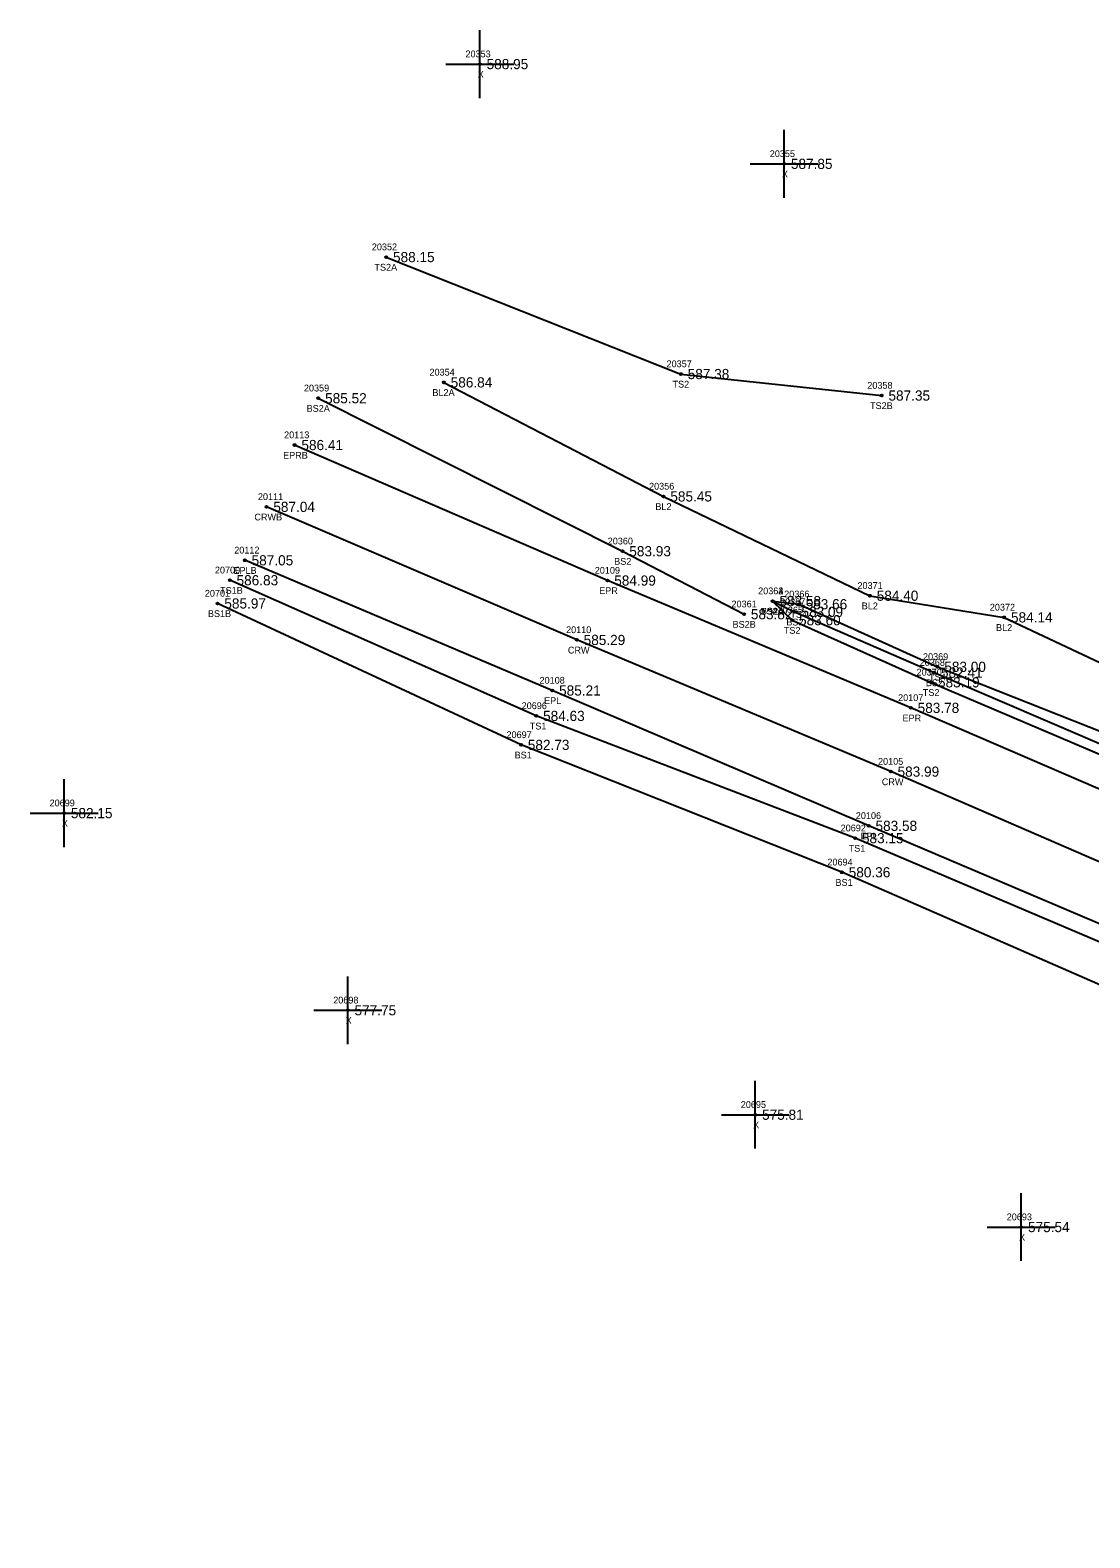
# Model space of a CAD drawing. Extents: x 1664837 to 1666270, y 987403 to 988245.
# Drawn here: x 1664836.6 to 1664992.8, y 987882.7 to 988105 of the extents above; entities that cross this region are included whole.
import ezdxf

# ---------------------------------------------------------------- set-up
doc = ezdxf.new("R2010")
doc.units = 0
for name, color, linetype in [('RD_DTM_BkLn1', 7, 'Continuous'), ('RD_DTM_BkLn2', 7, 'Continuous'), ('RD_DTM_BkLn_txCode', 7, 'Continuous'), ('RD_EX_Misc', 7, 'Continuous'), ('RD_EX_Misc_txCode', 7, 'Continuous'), ('RD_EX_Road', 7, 'Continuous'), ('RD_EX_Road_txCode', 7, 'Continuous'), ('RD_EX_TX_Misc_ELEV', 7, 'Continuous'), ('RD_EX_TX_Road_ELEV', 7, 'Continuous'), ('RD_HC_Survey_ELEV', 7, 'Continuous'), ('RD_HC_Survey_txCode', 7, 'Continuous'), ('RD_SMD_Locator', 7, 'Continuous')]:
    doc.layers.add(name, color=color, linetype=linetype)

msp = doc.modelspace()

# ---------------------------------------------------------------- linework, layer by layer
at = {"layer": 'RD_DTM_BkLn1'}
for points in [[(1664897.55, 988053.04), (1664929.93, 988036.23), (1664960.35, 988021.59), (1664980.14, 988018.4), (1665019.3, 987999.93), (1665066.16, 987977.43), (1665113, 987959.04), (1665120.17, 987953.31)], [(1665502.18, 987767.43), (1665469.18, 987781.68), (1665423.29, 987801.23), (1665377.17, 987820.37), (1665331.28, 987839.54), (1665285.44, 987859.03), (1665239.3, 987878.58), (1665193.14, 987897.86), (1665147.41, 987917.57), (1665101.07, 987936.7), (1665055.19, 987956.08), (1665009.23, 987975.83), (1664963.42, 987995.66), (1664917.15, 988015.07), (1664871.41, 988034.69)]]:
    msp.add_lwpolyline(points, dxfattribs=at)
at = {"layer": 'RD_DTM_BkLn2'}
for points in [[(1664889.05, 988071.51), (1664932.49, 988054.27), (1664962.08, 988051.1)], [(1664879.04, 988050.7), (1664923.88, 988028.15), (1664941.8, 988018.87)], [(1665078.62, 987914.97), (1665085.83, 987922.59), (1665086.28, 987928.53), (1665050.67, 987946.48), (1665006.64, 987965.25), (1664958.17, 987985.85), (1664911.17, 988003.87), (1664865.99, 988023.87)], [(1665078.62, 987914.97), (1665081.14, 987924.09), (1665045.5, 987937.96), (1665003.99, 987959.93), (1664956.22, 987980.82), (1664908.92, 987999.6), (1664864.19, 988020.45)], [(1664946.01, 988020.8), (1664948.9, 988017.98), (1664969.38, 988008.82), (1665013.94, 987989.82), (1665062.21, 987968.67), (1665107.8, 987949.81), (1665129.74, 987938.23)], [(1664946.01, 988020.8), (1664949.25, 988019.2), (1664969.82, 988010.25), (1665014, 987991.29), (1665063.08, 987970.03), (1665108.53, 987951.41), (1665133.21, 987942.56)], [(1664946.01, 988020.8), (1664949.87, 988020.34), (1664970.31, 988011.11), (1665015, 987993.44), (1665063.25, 987971.06), (1665108.56, 987952.04), (1665120.17, 987953.31), (1665135.91, 987946.31)]]:
    msp.add_lwpolyline(points, dxfattribs=at)
at = {"layer": 'RD_EX_Misc'}
for p, q in [((1664902.85, 988094.96), (1664902.85, 988104.96)), ((1664897.85, 988099.96), (1664907.85, 988099.96)), ((1664947.7, 988080.25), (1664947.7, 988090.25)), ((1664942.7, 988085.25), (1664952.7, 988085.25)), ((1664841.57, 987984.54), (1664841.57, 987994.54)), ((1664836.57, 987989.54), (1664846.57, 987989.54)), ((1664883.38, 987955.48), (1664883.38, 987965.48)), ((1664878.38, 987960.48), (1664888.38, 987960.48)), ((1664943.45, 987940.08), (1664943.45, 987950.08)), ((1664938.45, 987945.08), (1664948.45, 987945.08)), ((1664982.65, 987923.52), (1664982.65, 987933.52)), ((1664977.65, 987928.52), (1664987.65, 987928.52))]:
    msp.add_line(p, q, dxfattribs=at)
at = {"layer": 'RD_EX_Road'}
for points in [[(1665506.06, 987776.52), (1665471.95, 987789.57), (1665426.52, 987809.19), (1665380.33, 987828.78), (1665335.61, 987847.53), (1665288.25, 987866.82), (1665242.34, 987886.56), (1665197.07, 987906.16), (1665152.2, 987925.43), (1665127.55, 987936.7), (1665104.5, 987945.2), (1665059.19, 987965.3), (1665013.63, 987984.66), (1664966.38, 988005.06), (1664921.66, 988023.83), (1664875.55, 988043.8)], [(1665498.75, 987759.37), (1665465.87, 987774.2), (1665419.78, 987793.88), (1665373.62, 987813.14), (1665327.95, 987832.31), (1665281.42, 987852.3), (1665236.13, 987871.34), (1665189.6, 987890.71), (1665143.92, 987909.97), (1665117.43, 987920.99), (1665086.22, 987934.27), (1665051.62, 987948.55), (1665005.38, 987968.44), (1664960.17, 987987.67), (1664913.53, 988007.62), (1664868.21, 988026.81)]]:
    msp.add_lwpolyline(points, dxfattribs=at)
at = {"layer": 'RD_SMD_Locator'}
for centre in [(1664902.85, 988099.96), (1664947.7, 988085.25), (1664889.05, 988071.51), (1664932.49, 988054.27), (1664897.55, 988053.04), (1664879.04, 988050.7), (1664962.08, 988051.1), (1664875.55, 988043.8), (1664929.93, 988036.23), (1664871.41, 988034.69), (1664923.88, 988028.15), (1664868.21, 988026.81), (1664865.99, 988023.87), (1664921.66, 988023.83), (1664946.01, 988020.8), (1664946.01, 988020.8), (1664946.01, 988020.8), (1664960.35, 988021.59), (1664864.19, 988020.45), (1664941.8, 988018.87), (1664949.25, 988019.2), (1664949.87, 988020.34), (1664948.9, 988017.98), (1664980.14, 988018.4), (1664917.15, 988015.07), (1664969.82, 988010.25), (1664970.31, 988011.11), (1664913.53, 988007.62), (1664969.38, 988008.82), (1664911.17, 988003.87), (1664966.38, 988005.06), (1664908.92, 987999.6), (1664963.42, 987995.66), (1664841.57, 987989.54), (1664960.17, 987987.67), (1664958.17, 987985.85), (1664956.22, 987980.82), (1664883.38, 987960.48), (1664943.45, 987945.08), (1664982.65, 987928.52)]:
    msp.add_circle(centre, 0.15, dxfattribs=at)

# ---------------------------------------------------------------- texts
at = {"layer": 'RD_DTM_BkLn_txCode'}
for s, p in [('20352', (1664886.93, 988072.51)), ('TS2A', (1664887.32, 988069.51)), ('20354', (1664895.43, 988054.04)), ('20357', (1664930.37, 988055.27)), ('20359', (1664876.92, 988051.7)), ('BL2A', (1664895.86, 988051.04)), ('TS2', (1664931.25, 988052.27)), ('20358', (1664959.96, 988052.1)), ('BS2A', (1664877.32, 988048.7)), ('TS2B', (1664960.36, 988049.1)), ('20356', (1664927.79, 988037.23)), ('BL2', (1664928.72, 988034.23)), ('20360', (1664921.7, 988029.15)), ('20700', (1664863.8, 988024.87)), ('BS2', (1664922.65, 988026.15)), ('20371', (1664958.51, 988022.59)), ('20701', (1664862.32, 988021.45)), ('TS1B', (1664864.56, 988021.87)), ('20361', (1664939.94, 988019.87)), ('20362', (1664943.87, 988021.8)), ('20363', (1664943.87, 988021.8)), ('20364', (1664943.87, 988021.8)), ('20367', (1664947.11, 988020.2)), ('20366', (1664947.71, 988021.34)), ('BS1B', (1664862.77, 988018.45)), ('TS2A', (1664944.28, 988018.8)), ('TS4A', (1664944.28, 988018.8)), ('BS2A', (1664944.29, 988018.8)), ('20365', (1664946.76, 988018.98)), ('TS4', (1664948.63, 988018.34)), ('BL2', (1664959.14, 988019.59)), ('20372', (1664978.02, 988019.4)), ('BS2B', (1664940.1, 988016.87)), ('TS2', (1664947.66, 988015.98)), ('BS2', (1664948.02, 988017.2)), ('BL2', (1664978.94, 988016.4)), ('20368', (1664967.68, 988011.25)), ('20369', (1664968.17, 988012.11)), ('20370', (1664967.22, 988009.82)), ('TS4', (1664969.07, 988009.11)), ('TS2', (1664968.14, 988006.82)), ('BS2', (1664968.59, 988008.25)), ('20696', (1664909.01, 988004.87)), ('20697', (1664906.78, 988000.6)), ('TS1', (1664910.21, 988001.87)), ('BS1', (1664907.98, 987997.6)), ('20692', (1664956.03, 987986.85)), ('TS1', (1664957.21, 987983.85)), ('20694', (1664954.08, 987981.82)), ('BS1', (1664955.27, 987978.82))]:
    msp.add_text(s, height=1, dxfattribs=at).set_placement(p)
at = {"layer": 'RD_EX_Misc_txCode'}
for s, p in [('20353', (1664900.73, 988100.96)), ('X', (1664902.54, 988097.96)), ('20355', (1664945.58, 988086.25)), ('X', (1664947.38, 988083.25)), ('20699', (1664839.43, 987990.54)), ('X', (1664841.25, 987987.54)), ('20698', (1664881.24, 987961.48)), ('X', (1664883.07, 987958.48)), ('20695', (1664941.31, 987946.08)), ('X', (1664943.13, 987943.08)), ('20693', (1664980.51, 987929.52)), ('X', (1664982.33, 987926.52))]:
    msp.add_text(s, height=1, dxfattribs=at).set_placement(p)
at = {"layer": 'RD_EX_Road_txCode'}
for s, p in [('20113', (1664874, 988044.8)), ('EPRB', (1664873.85, 988041.8)), ('20112', (1664866.65, 988027.81)), ('EPLB', (1664866.53, 988024.81)), ('20109', (1664919.79, 988024.83)), ('EPR', (1664920.44, 988021.83)), ('20108', (1664911.65, 988008.62)), ('EPL', (1664912.32, 988005.62)), ('20107', (1664964.5, 988006.06)), ('EPR', (1664965.15, 988003.06)), ('20106', (1664958.27, 987988.67)), ('EPL', (1664958.97, 987985.67))]:
    msp.add_text(s, height=1, dxfattribs=at).set_placement(p)
at = {"layer": 'RD_EX_TX_Misc_ELEV'}
for s, p in [('588.95', (1664903.85, 988099.21)), ('587.85', (1664948.7, 988084.5)), ('588.15', (1664890.05, 988070.76)), ('587.38', (1664933.49, 988053.52)), ('586.84', (1664898.55, 988052.29)), ('585.52', (1664880.04, 988049.95)), ('587.35', (1664963.08, 988050.35)), ('585.45', (1664930.93, 988035.48)), ('583.93', (1664924.88, 988027.4)), ('586.83', (1664866.99, 988023.12)), ('585.97', (1664865.19, 988019.7)), ('583.58', (1664947.01, 988020.05)), ('583.58', (1664947.01, 988020.05)), ('583.58', (1664947.01, 988020.05)), ('583.66', (1664950.87, 988019.59)), ('584.40', (1664961.35, 988020.84)), ('583.82', (1664942.8, 988018.12)), ('583.60', (1664949.9, 988017.23)), ('583.09', (1664950.25, 988018.45)), ('584.14', (1664981.14, 988017.65)), ('582.41', (1664970.82, 988009.5)), ('583.00', (1664971.31, 988010.36)), ('583.19', (1664970.38, 988008.07)), ('584.63', (1664912.17, 988003.12)), ('582.73', (1664909.92, 987998.85)), ('582.15', (1664842.57, 987988.79)), ('583.15', (1664959.17, 987985.1)), ('580.36', (1664957.22, 987980.07)), ('577.75', (1664884.38, 987959.73)), ('575.81', (1664944.45, 987944.33)), ('575.54', (1664983.65, 987927.77))]:
    msp.add_text(s, height=1.5, dxfattribs=at).set_placement(p)
at = {"layer": 'RD_EX_TX_Road_ELEV'}
for s, p in [('586.41', (1664876.55, 988043.05)), ('587.05', (1664869.21, 988026.06)), ('584.99', (1664922.66, 988023.08)), ('585.21', (1664914.53, 988006.87)), ('583.78', (1664967.38, 988004.31)), ('583.58', (1664961.17, 987986.92))]:
    msp.add_text(s, height=1.5, dxfattribs=at).set_placement(p)
at = {"layer": 'RD_HC_Survey_ELEV'}
for s, p in [('587.04', (1664872.41, 988033.94)), ('585.29', (1664918.15, 988014.32)), ('583.99', (1664964.42, 987994.91))]:
    msp.add_text(s, height=1.5, dxfattribs=at).set_placement(p)
at = {"layer": 'RD_HC_Survey_txCode'}
for s, p in [('20111', (1664870.14, 988035.69)), ('CRWB', (1664869.62, 988032.69)), ('20110', (1664915.56, 988016.07)), ('CRW', (1664915.83, 988013.07)), ('20105', (1664961.54, 987996.66)), ('CRW', (1664962.1, 987993.66))]:
    msp.add_text(s, height=1, dxfattribs=at).set_placement(p)

doc.saveas('drawing.dxf')
